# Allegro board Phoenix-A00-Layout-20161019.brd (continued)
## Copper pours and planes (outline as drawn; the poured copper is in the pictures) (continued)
+3P3V_SB_PHASE_R on TOP (solid shape): 59.72,55.02 59.72,53.16 59.6,53.04 58.61,53.04 58.5,53.14 58.5,54.16 58.5,54.2 58.25,54.46 58.25,55.73 58.33,55.8 58.94,55.8
+3P3V_SB_UG25 on TOP (solid shape): 52.29,48.24 52.29,47.42 52.11,47.23 51.71,47.23 51.49,47.3 51.28,47.23 50.76,47.23 50.51,47.49 50.51,47.93 50.97,48.39 52.15,48.39
+3P3V_SB_UG25 on BOTTOM (solid shape): 47.9,53.37 47.9,53.1 47.49,52.69 47.49,52.2 48.68,51.01 48.68,49.61 49.81,48.47 52.11,48.47 52.21,48.37 52.21,47.37 52.16,47.31 49.21,47.31 47.66,48.87 47.66,50.56 47.29,50.93 47.28,50.93 46.63,51.58 46.63,53.43 46.81,53.61 47.66,53.61
+3P3V_SB_UGR_25 on TOP (solid shape): 53.47,47.04 53.47,45.67 53.38,45.58 50.54,45.58 50.24,45.88 50.24,46.36 50.41,46.53 50.51,46.59 50.59,46.68 51.19,46.68 51.49,46.53 51.8,46.68 52.2,46.68 52.81,47.28 53.23,47.28
+5V/3P3V_VIN on TOP (solid shape): 49.69,55.73 49.69,54.94 49.46,54.71 47.77,54.71 47.7,54.78 46.92,54.78 46.12,53.99 46.12,53 46.06,52.93 46.01,52.93 45.93,53.01 45.93,54.64 46.29,54.99 46.29,55.52 46.54,55.78 47.07,55.78 47.15,55.86 47.63,55.86 47.78,56.01 49.41,56.01
+VCORE on TOP (solid shape): outline of 4359 points within 157.48,138.5 208.78,200.28
+VCORE on BOTTOM (solid shape): outline of 4218 points within 158.83,139.42 209.17,200.07
+VPP on TOP (solid shape): outline of 271 points within 88.9,69.86 99.68,95.61
+VPP_SW on TOP (solid shape): 97.95,75.95 97.95,75.39 99.32,74.02 99.32,70.59 100.03,69.88 102.12,69.88 102.27,69.72 102.27,69.52 102.17,69.42 101.18,69.42 100.9,69.14 100.9,68.29 100.43,67.82 97.69,67.82 95.28,70.23 95.28,75.01 96.35,76.07 97.82,76.07
+VPP_SW on L2_VCC: 97.67,67.82 95.28,70.21 95.28,74.95 96.4,76.07 100.13,76.07 100.36,75.84 100.36,74.15 99.35,73.13 99.35,70.63 100.26,69.72 100.47,69.72 100.52,69.77 102.06,69.77 102.32,69.51 102.32,69.17 102.06,68.91 101.55,68.91 101.22,68.58 101.15,68.58 100.38,67.82
+VPP_VIN on TOP (solid shape): 110.12,74.35 110.12,72.31 109.68,71.88 101.68,71.88 101.02,71.22 101.02,71.08 101.02,71.07 101,70.95 101.02,70.83 101.03,70.8 101.16,70.67 101.33,70.62 102.04,70.62 102.1,70.63 102.24,70.48 102.24,70.18 102.17,70.1 100.57,70.1 99.86,70.82 99.86,72.87 100.13,73.15 100.38,73.26 100.49,73.51 101,74.02 107.6,74.02 107.98,74.4 107.98,74.93 108.14,75.08 109.38,75.08
+VTT on TOP (solid shape): 159.93,88.03 159.93,87.17 159.93,87.17 159.93,86.87 159.69,86.67 159.59,86.39 159.63,86.08 159.83,85.84 159.85,85.82 159.89,85.74 159.86,85.66 159.8,85.6 159.5,85.6 159.28,85.37 159.28,84.77 159.22,84.62 159.23,84.46 159.23,83.8 159.89,83.14 159.89,81.97 159.45,81.53 159.45,80.81 159.8,80.46 159.8,79.65 159.81,79.64 159.81,78.58 159.42,78.19 159.42,74.42 159.16,74.17 159.16,71.63 158.78,71.25 156.12,71.25 155.61,71.75 155.61,76.45 155.99,76.84 155.99,83.93 156.02,84.01 156.11,84.03 156.15,84.02 156.19,84.02 156.29,84.02 156.83,84.56 156.29,85.09 156.19,85.09 156.15,85.09 156.11,85.08 156.02,85.11 155.99,85.18 155.99,86.61 157.89,88.52 159.44,88.52
+VTT on BOTTOM (solid shape): 160.03,92.38 160.03,91.72 159.09,90.78 159.09,88.87 159.85,88.11 159.85,87.4 159.67,87.22 158.53,87.22 158.33,87.43 158.33,92.13 158.76,92.56 159.85,92.56
A_GND on TOP (solid shape): 243.42,221.53 243.49,221.43 243.49,28.83 242.47,26.36 240,25.34 236,25.34 234.93,24.89 234.49,23.83 234.49,8.83 234.05,7.77 233,7.34 220.5,7.34 220.15,7.48 220.01,7.83 220.01,8.31 220.02,8.31 220.02,8.81 220,8.84 219.99,8.88 219.48,9.79 218.5,10.15 207.5,10.15 206.5,9.77 206,8.82 206,8.8 205.98,8.78 205.98,6.71 205.99,6.71 205.99,3.44 205.55,2.38 204.5,1.95 188.51,1.95 188.5,1.95 174.47,1.95 174.47,2.46 188.6,2.46 204.5,2.46 205.2,2.74 205.48,3.44 205.48,6.71 205.49,6.71 205.49,7.22 205.48,7.22 205.48,8.64 206.07,10.06 207.5,10.66 218.5,10.66 219.81,10.17 220.49,8.95 220.51,8.93 220.51,8.31 220.52,8.31 220.52,7.84 233,7.84 233.7,8.13 233.98,8.83 233.98,23.83 234.57,25.25 236,25.84 240,25.84 242.11,26.72 242.98,28.83 242.98,221.1 243.19,221.34 243.31,221.5
A_GND on BOTTOM (solid shape): 243.42,221.53 243.49,221.43 243.49,28.83 242.47,26.36 240,25.34 236,25.34 234.93,24.89 234.49,23.83 234.49,8.83 234.05,7.77 233,7.34 220.5,7.34 220.15,7.48 220.01,7.83 220.01,8.63 219.57,9.69 218.5,10.14 207.5,10.14 206.43,9.69 205.99,8.63 205.99,3.43 205.55,2.37 204.5,1.94 174.47,1.94 174.47,2.44 204.5,2.44 205.2,2.73 205.48,3.43 205.48,8.63 206.07,10.05 207.5,10.64 218.5,10.64 219.93,10.05 220.52,8.63 220.52,7.84 233,7.84 233.7,8.13 233.98,8.83 233.98,23.83 234.57,25.25 236,25.84 240,25.84 242.11,26.72 242.98,28.83 242.98,221.1 243.06,221.18 243.19,221.34 243.31,221.5
A_GND on L2_VCC: outline of 110 points within 170.72,1.94 243.49,258.32
A_GND on L3_GND: outline of 109 points within 170.72,1.94 243.49,258.32
A_PVDD1 on TOP (solid shape): 191.02,24.1 191.02,23.3 190.91,23.19 190.43,23.19 190.34,23.11 189.25,23.11 189.21,23.14 188.15,23.14 188.09,23.19 188.09,23.27 188.15,23.32 189.53,23.32 190.56,24.36 190.76,24.36
A_PVDD1 on TOP (solid shape): 194.88,29.09 194.88,25.71 195.02,25.57 195.02,24.04 194.68,23.71 193.95,23.71 193.66,24 193.66,24.21 193.35,24.53 193.35,27.63 193.34,27.63 192.87,28.1 192.25,28.1 191.92,27.77 191.59,27.77 191.53,27.83 191.53,28.27 191.53,28.28 191.55,28.4 191.53,28.52 191.53,28.53 191.53,28.97 192.02,29.47 194.5,29.47
A_PVDD1 on TOP (solid shape): 190.59,27.45 190.59,27.3 190.8,27.09 190.88,27.04 190.93,26.99 190.93,26.74 190.81,26.62 190.79,26.62 190.28,26.12 190.28,26.12 190.18,26.01 190.18,25.73 189.57,25.12 188.86,25.12 188.17,25.12 188.12,25.12 188.07,25.18 188.07,25.3 188.09,25.33 188.86,25.33 188.95,25.42 189.02,25.47 189.07,25.54 189.69,26.17 189.69,27.3 190.06,27.67 190.37,27.67
A_PVDD1 on BOTTOM (solid shape): 192.21,28.59 192.21,28.01 191.96,27.75 191.89,27.76 191.58,27.7 191.42,27.42 191.42,27.4 191.23,27.21 191.23,23.45 191,23.22 189.81,23.22 189.67,23.36 189.67,23.69 189.75,23.78 189.75,26.14 189.81,26.38 189.75,26.61 189.75,27.41 191.27,28.93 191.88,28.93
CLASSD_L+ on TOP (solid shape): 192.82,25.12 192.82,24.68 192.68,24.54 192.39,24.54 192.04,24.19 191.16,24.19 190.81,24.54 190.57,24.54 189.92,23.89 189.81,23.89 189.45,23.53 188.12,23.53 188.06,23.59 188.06,23.68 188.11,23.73 189.22,23.73 190.86,25.37 192.57,25.37
CLASSD_L+ on BOTTOM (solid shape): 192.81,25.15 192.81,24.65 192.37,24.21 191.8,24.21 191.68,24.34 191.68,25.23 191.77,25.32 192.64,25.32
CLASSD_L- on TOP (solid shape): 192.35,26.44 192.68,26.44 192.82,26.3 192.82,25.76 192.66,25.59 190.89,25.59 189.23,23.93 189.19,23.93 188.11,23.93 188.07,23.97 188.07,24.1 188.1,24.13 188.96,24.13 189.11,24.28 189.11,24.41 190.36,25.66 190.36,25.96 191.17,26.76 192.04,26.76
CLASSD_L- on BOTTOM (solid shape): 192.81,26.35 192.81,25.99 192.41,25.59 191.83,25.59 191.67,25.75 191.67,26.65 191.79,26.77 192.39,26.77
CPU_FAN_+12V on TOP (solid shape): outline of 246 points within 226.91,122.87 239.56,130.3
D1_1 on TOP (solid shape): 172.51,55.87 172.51,55.5 172.07,55.06 172.07,53.26 172.22,53.11 172.55,53.11 172.91,52.76 172.91,52.1 172.68,51.87 171.41,51.87 170.16,53.11 170.16,54 170.29,54.13 170.82,54.13 171.08,54.38 171.08,55.03 172.06,56.01 172.37,56.01
F_SPI_VCC on TOP (solid shape): 31.61,105.92 38.77,105.92 38.9,105.79 38.9,105.03 39.28,104.65 40.53,104.65 41,104.18 41,102.93 40.6,102.53 37.62,102.53 36.64,103.5 31.15,103.5 31.14,103.52 30.67,103.05 30.34,103.05 30.11,103.28 30.11,104.32 29.78,104.65 28.83,104.65 28.47,105 28.47,107.24 28.48,107.28 28.48,107.33 28.67,107.51 30.02,107.51
F_SPI_VCC on TOP (solid shape): outline of 85 points within 28.17,87.15 41.84,93.44
F_SPI_VCC on BOTTOM (solid shape): 40.18,103.52 41.2,103.52 42.5,102.22 42.5,101.03 42.49,101.01 42.45,100.85 42.48,100.7 42.52,100.62 42.57,100.56 43.16,99.97 43.16,92.51 42.46,91.82 40.85,91.82 40.37,92.3 40.37,92.86 40.55,93.05 40.71,93.05 40.72,93.04 41.98,93.63 41.13,94.73 41.06,94.76 41.03,94.83 41.03,99.98 40.93,100.08 40.88,100.16 40.8,100.22 40.8,100.56 40.93,100.84 40.8,101.12 40.8,101.96 39.91,102.85 39.91,103.31 40.12,103.52 40.17,103.52
FAN_CPU_PIN1 on TOP (solid shape): outline of 94 points within 233.46,129.16 239.81,135.64
FAN_CPU_PWM on TOP (solid shape): 239.81,136.78 239.81,132.21 239.68,132.08 237.59,132.08 237.02,132.65 237.02,134.11 237.9,135 237.9,136.78 238.03,136.91 239.68,136.91
Net_11 on TOP (solid shape): outline of 232 points within 188.51,161.95 194.51,167.95
Net_12 on TOP (solid shape): outline of 232 points within 188.51,125.95 194.51,131.95
Net_13 on TOP (solid shape): outline of 232 points within 127.49,143.95 133.49,149.95
Net_14 on BOTTOM (solid shape): outline of 232 points within 188.51,161.95 194.51,167.95
Net_15 on BOTTOM (solid shape): outline of 232 points within 188.51,125.95 194.51,131.95
Net_16 on BOTTOM (solid shape): outline of 232 points within 127.49,143.95 133.49,149.95
Net_26 on BOTTOM (solid shape): 217.37,14.2 215.45,14.2 214.59,15.06 213.73,14.2 212.25,14.2 211.39,15.06 210.53,14.2 210.27,14.2 210.27,15.2 215.87,15.2 215.87,17.7 217.37,17.7
Net_29 on TOP (solid shape): outline of 255 points within 233.59,221.74 241.71,229.87
Net_29 on BOTTOM (solid shape): outline of 255 points within 233.59,221.74 241.71,229.87
Net_78 on BOTTOM (solid shape): 221.76,247.67 220.77,249.63 221.76,251.6
O_+12VCOM on TOP (solid shape): 182.28,236.6 182.28,234.37 182.2,234.29 182.2,234.04 182.28,233.96 182.28,232.66 182.15,232.54 179.74,232.54 178.6,233.68 178.6,235.33 179.99,236.73 182.15,236.73
O_-12VCOM on TOP (solid shape): 181.77,226.95 181.77,223.27 181.64,223.14 178.47,223.14 178.34,223.27 178.34,225.15 178.39,225.2 178.39,225.73 178.47,225.81 179.48,225.81 179.74,226.06 179.74,226.82 179.99,227.08 181.64,227.08
PQ21B_D1 on TOP (solid shape): 97.91,64.77 98,64.77 98.43,64.34 98.82,64.34 98.94,64.24 99.09,64.2 99.6,64.2 99.64,64.2 99.8,64.03 99.8,63.07 99.5,62.76 97.59,62.76 97.37,62.99 97.36,62.99 96.17,64.18 96.17,64.93 96.42,65.18 97.5,65.18
PQ53_G1 on TOP (solid shape): 58.98,35.5 58.98,34.52 58.75,34.3 56.96,34.3 56.78,34.49 56.78,35.46 56.91,35.59 58.89,35.59
PQ71_D1 on TOP (solid shape): 11.75,41.78 13.37,41.78 13.62,41.53 13.62,40.57 12.67,39.62 10.85,39.62 8.62,41.85 8.16,41.85 8.04,42.06 7.83,42.16 7.83,42.91 7.41,43.33 6.48,43.33 6.43,43.37 6.43,43.7 6.51,43.78 9.75,43.78
PQ72B_E1 on TOP (solid shape): 234.6,57.9 234.6,57.01 234.13,56.54 233.62,56.54 233.42,56.34 233.42,55.68 233.32,55.58 232.79,55.58 232.54,55.83 232.54,58.08 232.82,58.36 234.14,58.36
REGOUT on TOP (solid shape): 113.23,224.5 113.23,224.49 113.3,224.39 113.4,224.32 113.42,224.31 113.5,224.29 113.58,224.28 113.93,224.28 114.1,224.1 114.35,224.06 115.15,223.26 115.37,223.26 115.38,223.25 117.78,223.25 118.12,222.91 119.44,222.91 119.62,222.73 119.62,221.59 119.44,221.41 114.94,221.41 114.64,221.72 114.64,222.38 113.85,223.17 113.33,223.17 112.87,223.62 112.87,224 112.33,224.54 112.3,224.54 111.95,224.89 111.95,225.45 112.05,225.55 112.17,225.55
RING2 on TOP (solid shape): 177.1,26.43 177.1,26.06 177.55,25.61 178.75,25.61 178.88,25.48 180.31,25.48 180.58,25.21 180.77,25.01 181.04,24.99 181.15,24.88 181.15,24.79 181.03,24.67 177.31,24.67 177.29,24.68 177.11,24.68 176.71,25.08 176.13,25.08 175.76,25.45 175.76,26.69 175.97,26.9 176.64,26.9
RING2_J on TOP (solid shape): 174.27,26.03 175.23,26.03 175.47,25.78 175.47,25.26 175.24,25.03 172.46,25.03 172.46,25.03 172.23,25.03 172.14,25.12 172.14,26.74 172.34,26.94 173.36,26.94
RING2_J on TOP (solid shape): 188.63,6.83 188.7,6.81 188.78,6.81 188.91,6.68 188.91,3.82 187.69,2.6 185.81,2.6 184.69,3.72 184.69,5.82 185.07,6.2 186.59,6.2 187.11,5.96 187.64,6.2 187.67,6.2 188.3,6.83
RING2_J on BOTTOM (solid shape): 173.34,26.7 173.34,26.16 175.83,23.67 175.83,21.93 177.61,20.15 177.61,16.09 178.04,15.65 178.04,13.65 177.87,13.36 177.81,13.04 177.81,12.25 178.08,11.6 178.73,11.34 178.79,11.34 184.16,5.98 186.26,5.98 187.52,4.72 187.52,3.67 186.45,2.59 185,2.59 183.68,3.91 183.32,4.46 182.72,4.74 178.8,8.67 178.56,9.08 178.15,9.32 176.38,11.09 176.38,19.45 175.65,20.18 175.53,20.38 175.33,20.5 174.03,21.8 174.03,23.31 172.18,25.16 172.18,26.78 172.31,26.91 173.13,26.91
SIO_CAP1 on TOP (solid shape): 209.81,38.53 209.81,38.46 209.31,37.96 208.82,37.54 209.4,37.27 210.27,36.4 210.3,36.29 210.4,36.21 210.4,35.66 210.24,35.51 210.04,35.51 209.66,35.89 208.8,35.89 208.64,36.04 208.64,36.27 208.26,36.65 208.26,38.46 208.39,38.58 209.76,38.58
SLEEVE on TOP (solid shape): 176.81,24.49 180.98,24.49 181.07,24.41 181.07,24.08 181.04,24.05 180.4,24.05 180.11,23.76 176.36,23.76 176.04,23.45 175.79,23.34 175.67,23.08 175.4,22.81 175.01,22.81 174.9,22.92 174.9,23.16 175.08,23.33 175.32,23.33 175.87,23.88 175.87,24.35 176.14,24.62 176.68,24.62
SLEEVE_J on TOP (solid shape): 175.47,24.46 175.47,23.93 175.17,23.63 174.49,23.63 174.33,23.47 174.05,23.47 173.72,23.15 173.72,22.86 173.41,22.55 173.08,22.55 173.01,22.56 172.94,22.55 172.31,22.55 172.25,22.56 172.14,22.56 172.09,22.62 172.09,23 172.14,23.06 172.14,24.31 172.53,24.7 175.24,24.7
SLEEVE_J on TOP (solid shape): 178.06,5.8 178.06,5.63 178.07,5.61 178.08,5.49 178.12,5.37 178.13,5.36 178.13,5.14 178.74,4.46 179.48,4.99 179.5,5.06 179.5,5.13 180.18,5.13 180.19,5.12 180.64,5.12 181.12,4.64 181.12,3.53 180.29,2.7 178.1,2.7 176.24,4.57 176.24,6.75 176.39,6.9 176.97,6.9
SLEEVE_J on BOTTOM (solid shape): outline of 194 points within 172.06,2.7 181.13,23.71
SPI_VDD1 on TOP (solid shape): 38.13,100.46 38.9,100.46 39.02,100.33 39.02,98.04 38.9,97.92 38.34,97.92 37.75,97.33 37.75,96.55 37.63,96.32 37.68,96.07 37.63,96.01 36.86,96.01 36.74,96.14 36.74,98.04 36.61,98.17 36.61,98.68 36.74,98.81 37.52,98.81 38.01,99.29 38.01,99.59 37.34,100.26 37.34,100.5 37.5,100.65 37.94,100.65
SYS_FAN_+12V on TOP (solid shape): 216.31,232.66 216.31,229.11 217.2,228.22 217.2,225.3 217.08,225.17 214.66,225.17 214.54,225.3 214.54,232.66 214.66,232.79 216.19,232.79
SYSTEM_FAN22 on TOP (solid shape): outline of 102 points within 198.41,221.4 214.28,233.3
SYSTEM_FAN23 on TOP (solid shape): 203.11,227.77 203.11,225.43 201.2,223.52 201.2,221.87 201.33,221.74 201.96,221.74 202.09,221.62 202.09,221.17 201.83,220.91 199.02,220.91 198.92,221.02 198.92,224.92 200.69,226.69 200.69,227.84 201.07,228.22 202.66,228.22
USBPWR0_F_50 on TOP (solid shape): outline of 529 points within 129.6,8.28 140.89,28.52
USBPWR0_F_50 on BOTTOM (solid shape): outline of 81 points within 137.59,18.86 152.05,21.36
USBPWR1_F_50 on TOP (solid shape): 138.08,231.29 138.08,230.25 136.15,228.32 131.78,228.32 131.43,228.68 131.43,230.02 131.47,230.06 131.47,230.62 131.61,230.76 136.27,230.76 136.28,230.68 136.29,230.6 136.31,230.53 136.34,230.45 136.37,230.38 136.42,230.32 136.46,230.26 136.52,230.2 136.58,230.15 136.65,230.1 136.71,230.07 136.79,230.04 136.86,230.02 136.94,230 137.02,230 137.1,230 137.17,230.01 137.25,230.03 137.33,230.05 137.4,230.09 137.46,230.13 137.53,230.17 137.58,230.23 137.64,230.29 137.68,230.35 137.72,230.42 137.75,230.49 137.78,230.56 137.79,230.64 137.8,230.72 137.8,230.8 137.79,230.88 137.78,230.95 137.75,231.03 137.72,231.1 137.68,231.17 137.64,231.23 137.58,231.29 137.53,231.35 137.46,231.39 137.4,231.43 137.33,231.47 137.25,231.49 137.17,231.51 137.1,231.52 137.02,231.52 136.94,231.52 136.86,231.5 136.79,231.48 136.71,231.45 136.65,231.41 136.58,231.37 136.52,231.32 136.46,231.26 136.42,231.2 136.37,231.13 136.34,231.06 136.31,230.99 136.29,230.92 136.28,230.84 136.27,230.76 131.61,230.76 132.57,231.72 137.65,231.72
USBPWR1_F_50 on TOP (solid shape): outline of 153 points within 137.07,235.23 145.45,249.12
USBPWR1_F_50 on BOTTOM (solid shape): outline of 410 points within 134.55,229.03 144,249.25
USBPWR4_F_50 on TOP (solid shape): outline of 249 points within 152.79,12.04 162.19,25.96
USBPWR5_F_50 on TOP (solid shape): 58.26,71.61 58.26,71.6 58.49,71.38 58.82,71.38 59.67,72.23 60.65,72.23 60.97,71.9 63.87,71.9 64.73,71.04 64.73,69.43 64.45,69.16 60.94,69.16 60.87,69.19 60.84,69.26 61.13,69.55 61.23,69.95 60.46,70.74 59.7,69.95 59.8,69.55 60.09,69.26 60.06,69.19 59.99,69.16 58.51,69.16 58.42,69.22 58.44,69.33 58.57,69.46 58.66,69.61 58.71,69.78 58.73,69.95 57.97,70.74 57.2,69.95 57.22,69.78 57.27,69.61 57.36,69.46 57.49,69.33 57.51,69.22 57.42,69.16 57.1,69.16 55.36,70.89 55.35,70.89 55.29,70.95 48.49,70.95 48.21,71.23 48.21,73.48 48.37,73.63 56.24,73.63
VGAPWR_F_20 on TOP (solid shape): outline of 187 points within 184.7,245.11 203.06,252.22
VGT_PHASE1_20 on TOP (solid shape): outline of 103 points within 213.53,157.05 225.72,171.44
VGT_PHASE1_20 on BOTTOM (solid shape): 225.46,171.29 225.46,167 223.68,165.23 223.68,162.69 224.95,161.42 224.95,157.59 224.6,157.24 213.82,157.24 213.51,157.55 213.51,163.82 216.85,167.16 217.72,167.16 219,165.88 219.83,165.88 220.07,166.12 220.12,166.12 220.38,166.37 220.38,167.23 219.16,168.45 219.16,169.47 221.13,171.44 225.32,171.44
VGT_PHASE1_20 on L2_VCC: 214.01,156.84 212.99,157.86 211.72,157.86 211.49,158.09 211.49,161.95 219.36,169.82 219.36,172.87 219.59,173.1 225.73,173.1 227.11,171.73 227.11,171.36 226.77,171.02 226.38,171.02 226.33,171.07 226.11,171.07 225.71,170.67 225.71,170.03 225.46,169.78 225.46,166.09 225.23,165.86 224.34,165.86 223.68,165.21 223.68,162.33 224.95,161.06 224.95,157.84 224.59,157.48 218.11,157.48 217.48,156.84
VGT_PHASE2_20 on TOP (solid shape): outline of 95 points within 212.76,139.29 225.71,153.67
VGT_PHASE2_20 on BOTTOM (solid shape): 225.59,152.68 225.59,145.03 223.91,143.36 223.91,139.42 223.68,139.19 213.14,139.19 212.76,139.57 212.76,144.14 217.14,148.53 217.95,148.53 219.23,147.25 220.05,147.25 220.38,147.57 220.38,147.83 220.36,147.84 220.36,148.81 219.38,149.8 219.38,150.89 221.29,152.81 225.46,152.81
VGT_PHASE2_20 on L2_VCC: 213.12,139.32 212.61,139.83 211.09,139.83 210.85,140.06 210.85,142.26 222.26,153.67 225.61,153.67 225.84,153.44 225.84,152.12 225.46,151.74 225.46,148.31 225.23,148.08 224.46,148.08 223.93,147.55 223.93,139.55 223.7,139.32
VRM_PHASE1_20 on TOP (solid shape): outline of 121 points within 195.99,198.88 211.77,211.84
VRM_PHASE1_20 on BOTTOM (solid shape): 210.95,210.63 210.95,205.14 211.48,204.61 211.48,200.83 210.8,200.15 206.76,200.15 206.44,200.47 206.44,202.53 205.52,203.45 203.59,203.45 203.31,203.74 203.31,204.09 203.2,204.2 202.58,204.2 202.57,204.19 202.09,204.19 201.93,204.04 201.93,203.94 201.79,203.8 198.06,203.8 196.38,205.49 196.38,207.2 196.61,207.43 197.04,207.43 197.76,208.15 197.76,209.41 198.46,210.11 202.6,210.11 203.42,209.29 206.08,209.29 206.78,209.99 206.78,210.67 207.11,211 210.58,211
VRM_PHASE1_20 on L2_VCC: 206.42,197.87 206.15,198.13 206.15,198.61 202.83,201.93 197.88,201.93 197.52,202.29 197.52,204.32 195.74,206.1 195.74,207.26 196.08,207.52 197.14,207.52 197.65,208.2 197.65,209.32 198.89,210.57 202.87,210.57 203.11,210.33 203.11,209.57 203.64,209.04 204.61,209.04 204.86,209.3 206.01,209.3 206.54,209.83 206.54,210.84 206.77,211.07 211.38,211.07 211.49,210.97 211.49,200.64 211,200.15 209.99,200.15 209.46,199.62 209.46,198.1 209.22,197.87
VRM_PHASE2_20 on TOP (solid shape): outline of 115 points within 179.07,191.13 193.86,205.74
VRM_PHASE2_20 on BOTTOM (solid shape): 193.84,196.47 193.84,192.53 193.71,192.41 189.92,192.41 189.69,192.63 189.69,196.47 189.85,196.62 193.68,196.62
VRM_PHASE2_20 on BOTTOM (solid shape): 193.84,204.22 193.84,199.92 193.56,199.64 188.7,199.64 186.8,197.74 186.8,196.01 185.94,195.15 185.42,195.15 184.78,195.8 184.74,195.8 184.57,195.97 184.17,195.97 183.02,194.82 180.25,194.82 179.74,195.33 179.74,201.93 178.98,202.69 178.98,204.22 179.61,204.85 184.56,204.85 185.58,203.83 188.25,203.83 188.88,204.47 188.88,205.36 189.01,205.49 192.57,205.49
VRM_PHASE2_20 on L2_VCC: 189.24,189.74 185.43,193.55 179.97,193.55 179.74,193.78 179.74,202.16 178.98,202.92 178.98,204.75 179.34,205.1 180.73,205.1 181.62,205.99 184.59,205.99 184.82,205.76 184.82,204.75 185.73,203.83 188.1,203.83 189.01,204.75 189.01,205.51 189.37,205.87 193.29,205.87 193.5,205.66 193.5,197.27 193.89,196.89 193.89,192.74 193.37,192.23 191.97,192.23 191.47,191.73 191.47,189.95 191.26,189.74
VRM_PHASE3_20 on TOP (solid shape): outline of 109 points within 161.59,186.56 176.18,205.87
VRM_PHASE3_20 on BOTTOM (solid shape): 167.67,205.23 167.67,204.72 169.2,203.2 170.59,203.2 171.61,202.18 175.67,202.18 176.18,201.68 176.18,193.32 175.85,192.99 175.85,188.87 175.56,188.58 172.29,188.58 171.64,189.23 171.64,191.08 168.23,194.49 167.54,194.49 167.3,194.72 167.3,195.15 167.56,195.4 167.56,195.85 166.83,196.58 166.46,196.58 165.45,195.58 165.45,194.77 165.12,194.44 161.58,194.44 161.45,194.56 161.45,201.29 161.96,201.8 161.96,205.1 162.59,205.74 167.17,205.74
VRM_PHASE3_20 on L2_VCC: 173.75,185.55 166.64,192.66 161.56,192.66 161.2,193.02 161.2,205.51 161.56,205.87 167.57,205.87 167.8,205.63 167.8,204.75 169.09,203.45 170.11,203.45 171.25,202.31 175.95,202.31 176.18,202.08 176.18,185.91 175.82,185.55
VRM_SN1_20 on TOP (solid shape): 209.46,199.64 209.46,197.99 209.33,197.87 206.79,197.87 206.66,197.99 206.66,198.5 206.79,198.63 207.81,198.63 208.06,198.88 208.06,199.64 208.19,199.77 209.33,199.77
VRM_SN2_20 on TOP (solid shape): 191.55,191.77 191.55,189.99 191.42,189.87 189.14,189.87 188.88,190.12 188.88,190.75 189.01,190.88 189.9,190.88 190.15,191.13 190.15,191.77 190.28,191.9 191.42,191.9
VRM_SN3_20 on TOP (solid shape): 176.06,187.07 176.06,185.91 175.82,185.67 173.76,185.67 173.62,185.81 173.62,186.24 173.68,186.31 174.4,186.31 174.66,186.56 174.66,187.07 174.79,187.2 175.93,187.2

Small or netless copper shapes (teardrops, artwork), in the pictures only: 519 on TOP, 2 on BOTTOM, 2 on L2_VCC

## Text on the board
User.Comments: CR_C_1 | CR_D_1 | CR_A_1 | CR_1_1 | CR_1_2 | CR_1_3 | SATA | TBT | F_USB3
Board Geometry/Outline: ECO NUMBER | 883479 | 2016/10/11 | PHOENIX-A00
Ref Des/Silkscreen Top: P2 | CMOS_CLR | 1-2 | SHORT:RTC_CMOS_RESET | OPEN:DEFAULT | P3 | 2 | SERVICE_MODE | 1 | 3 | 4 | 3-4 | 6 | SHORT:ME DISABLE | 5 | P1 | PASSWORD | _CLR | 5-6 | SHORT:DEFAULT | OPEN:PASSWORD RESET | E | D | F | C | G | R | Q | I | J | S | K | T | L | N | M | O | U | PX0606
BODY_CENTER: * | 23 | 17 | 7 | 4 | 8 | 5 | 3
User.23: 257.40 | 244.00
User.25: 257.40 | 244.00
User.31: 257.40 | 244.00
User.32: 257.40 | 234.00 | 125.00 | 244.00 | 252.00
User.34: 257.40 | 234.00 | 125.00 | 244.00 | 252.00
User.40: 257.40 | 234.00 | 125.00 | 244.00 | 252.00
User.45: USBPWR9_F_50 | 1P0V_PCH_PHASE | GND | +VPP_LX | VCCIO_PHASE | +3P3V_DUAL_LX_80 | 1P2V_SM__PHASE_25 | +3P3V_DUAL_PHASE_25 | GND_AUDIO | 1P0V_VCCAPLL_FB_R | 1P0V_PCH_VIN | +3P3V_MAIN | VCORE_SW3_25 | +5V_DUAL_USB | VCORE_SW2_25 | VCORE_SW1_25 | +VGT_SW2_25 | +VGT_SW1_25 | +3P3V_PCIAUX | +3P3V_SB | VCCSA_PHASE | +12V_CPU | +5VSB_NIC | +5V_MAIN | +3P3V_AUX | +12V_MAIN | +1P0V_PCH_AUX | +VDDQ | +VCCSA | +VCCIO | +12V_CPU_VIN | 1P2V_SM_VIN | ******************************************* | * Drill Tolerance:                        * | * 1.PTH : +/-3MILS                        * | * 2.NPTH: +/-2MILS                        * | * 3.Oblong Slot PTH : +/-3MILS            * | * 4.Oblong Slot NPTH:Short Side:+/-2MILS  * | *                    Long  Side:+/-3MILS  * | *                                         * | * Tooling/Mounting Hole Drill Tolerance:  * | * 1.PTH : +4/-0 MILS                      * | * 2.NPTH: +3/-0 MILS                      * | * 3.NPTH 125MILS : +2/-0 MILS             * | FIGURE | SIZE | 10.0 | 12.0 | 22.0 | 26.0 | 28.0 | 31.0 | 32.0 | 34.0 | 36.0 | 37.0 | 38.0 | 39.0 | 40.0 | 44.0 | 45.0 | 46.0 | 52.0 | 54.0 | 55.0 | 56.0 | 67.0 | 92.0 | 128.0 | 43.0 | 48.0 | 50.0 | 59.0 | 63.0 | 65.0 | 93.0 | 96.0 | 118.0 | 120.0 | 125.0 | 146.0 | 150.0 | 157.0 | 160.0 | 197.0 | 55.0x24.0 | 55.0x26.0 | 59.0x37.0 | 83.0x35.0 | 83.0x55.0 | 94.0x67.0 | 96.0x47.0 | 102.0x44.0 | 354.0x126.0 | DRILL CHART: TOP to BOTTOM | ALL UNITS ARE IN MILS | PLATED | NON-PLATED | QTY | 6278 | 894 | 19 | 576 | 57 | 204 | 6 | 4 | 44 | 13 | 12 | 24 | 2 | 67 | 240 | 22 | 26 | 3 | 1 | 5 | 20 | 8
